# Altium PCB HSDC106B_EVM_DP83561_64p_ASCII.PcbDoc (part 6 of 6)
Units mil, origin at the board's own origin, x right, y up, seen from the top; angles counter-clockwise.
Board outline 8750.24 x 6394.7 mil, 6 copper layers (Top Layer, GND, SIG1, SIG2, GND1, Bottom Layer), stack 60.4 mil thick; 475 components, 330 nets, 1628 pads, 1086 vias.
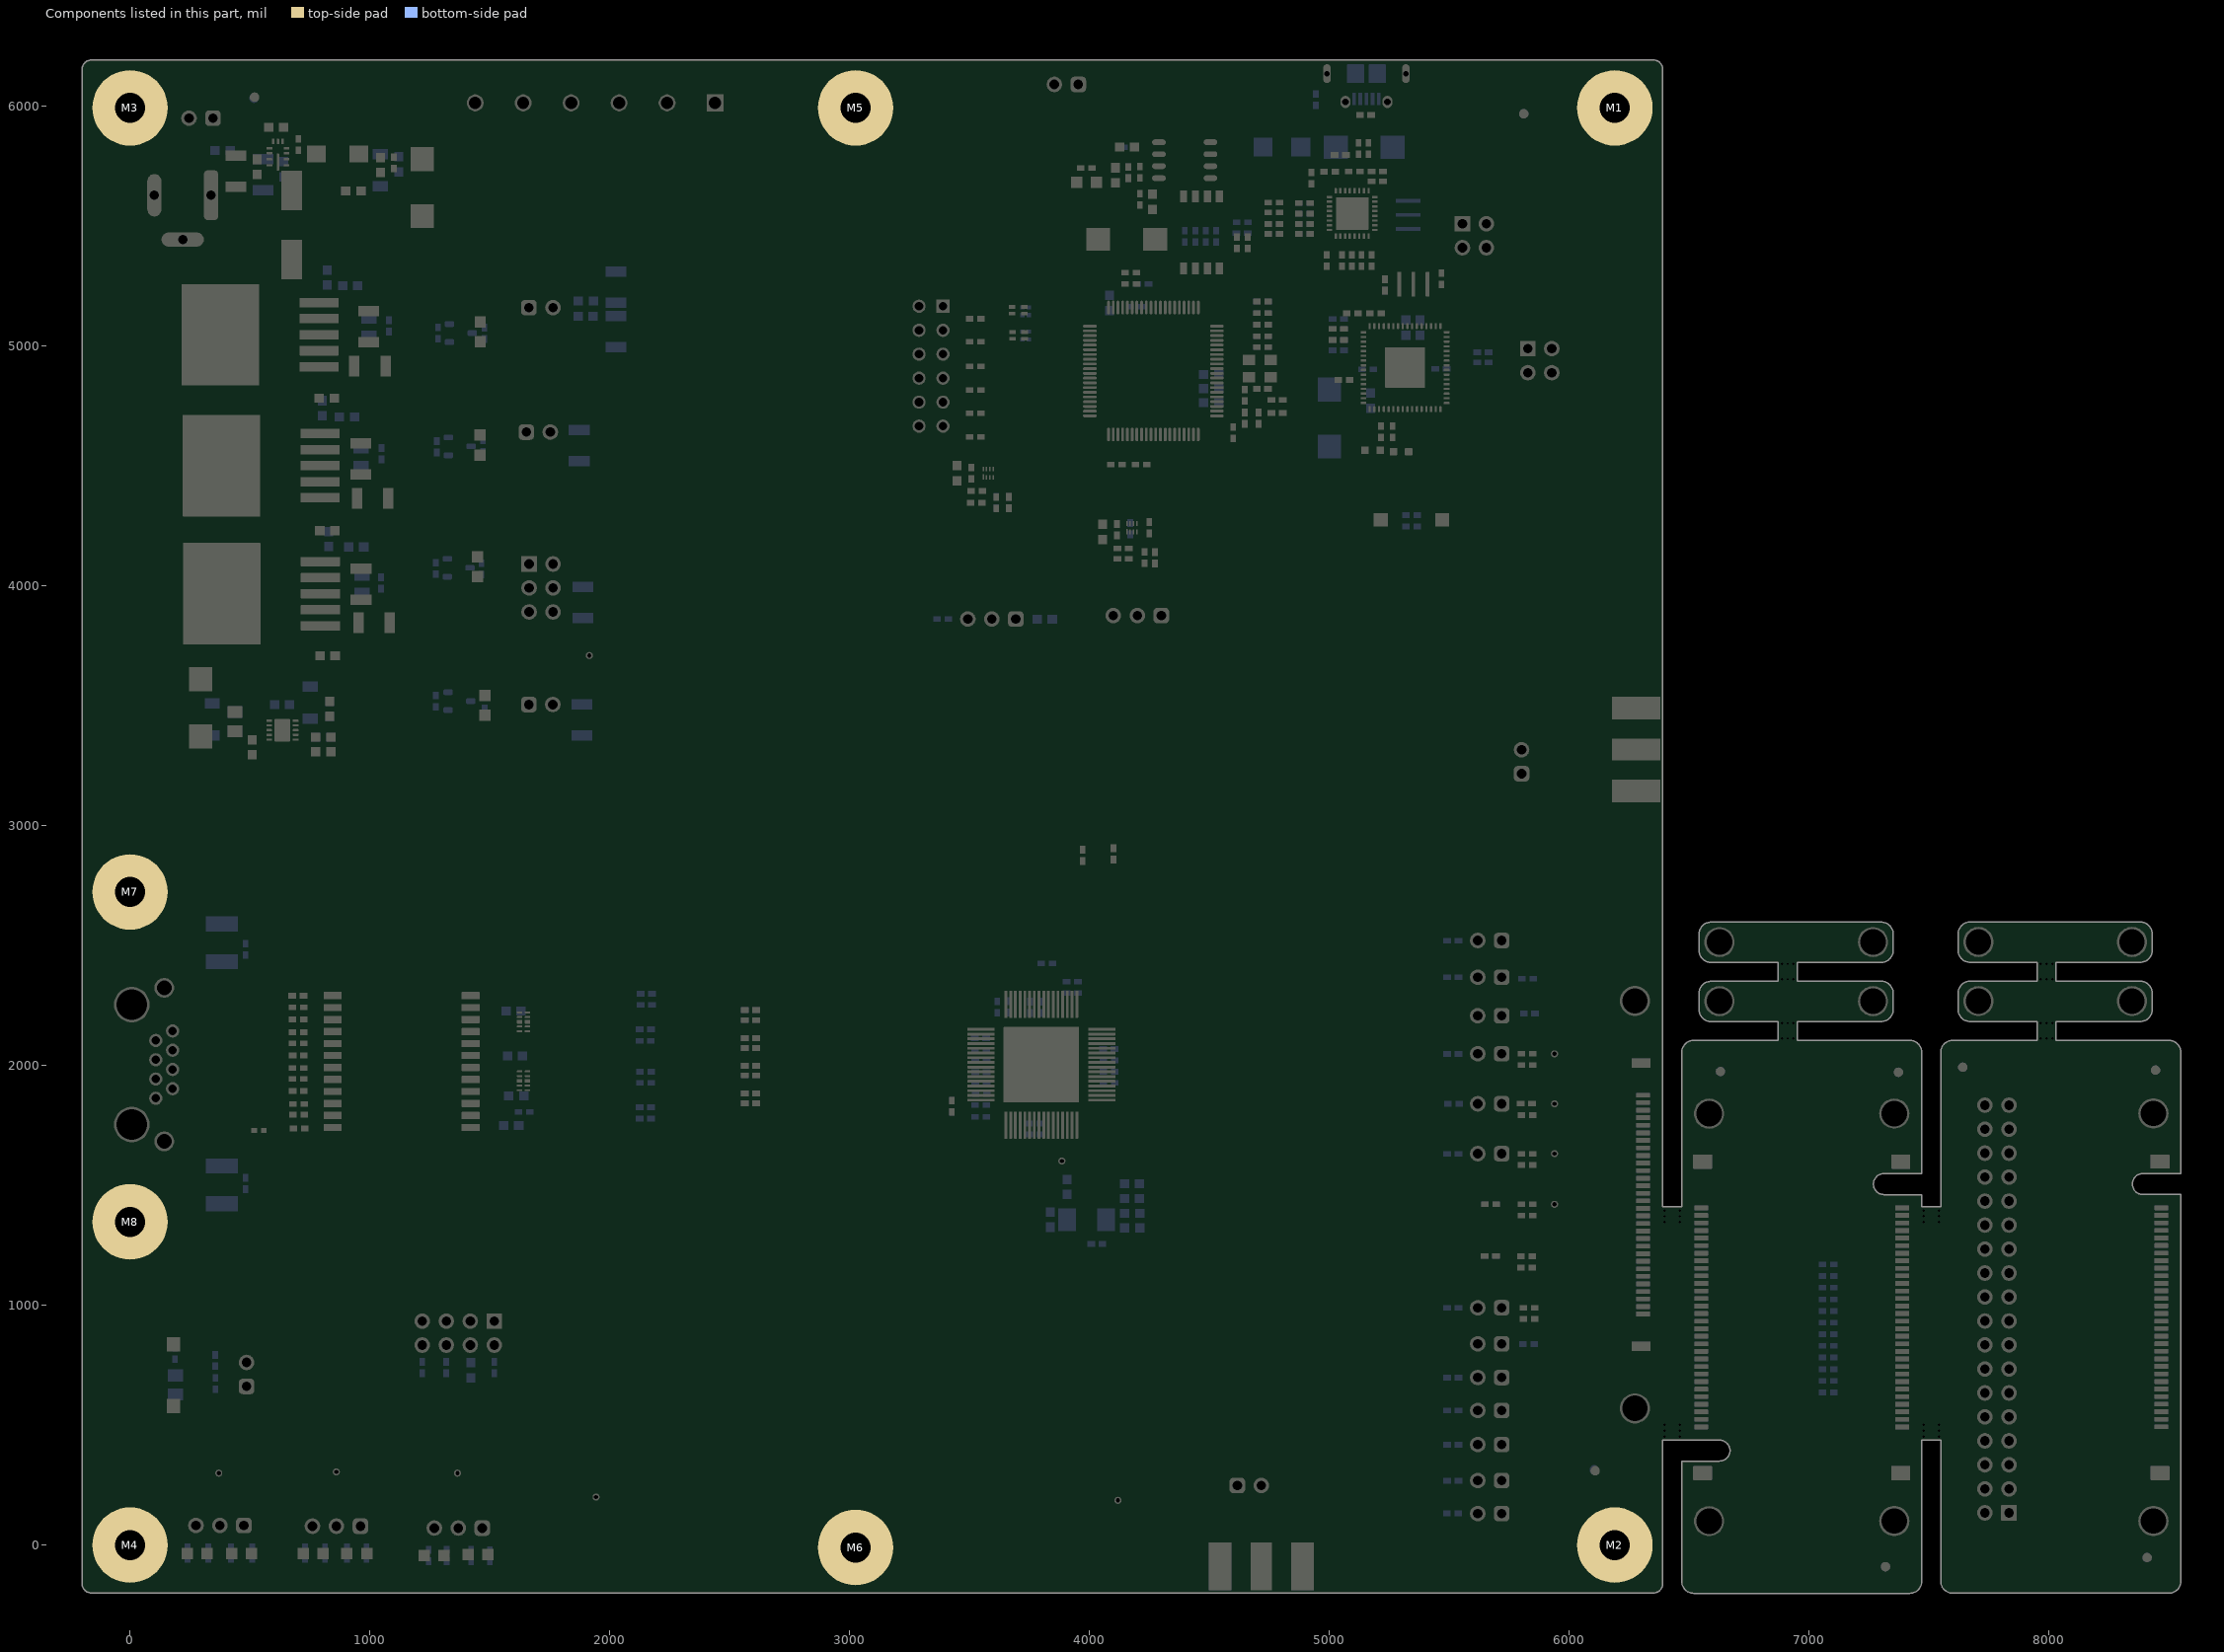
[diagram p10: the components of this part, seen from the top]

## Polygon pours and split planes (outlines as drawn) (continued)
5V-36V on Top Layer "5V-36V_L01_P641" (solid, remove dead copper, pour order 641): 405.6,5880.61 497.6,5880.61 564.6,5813.61 589.6,5813.61 592.6,5810.61 592.6,5776.61 590.6,5774.61 563.6,5774.61 534.6,5745.61 409.88,5745.61 396.6,5758.88 396.6,5871.61
5V-36V_jack on Top Layer "5V-36V_JACK_L01_P644" (solid, remove dead copper, pour order 644): 294.6,5968.61 294.6,5542.51 310.82,5526.29 363.62,5526.29 381.27,5543.94 381.27,5967.44 363.1,5985.61 311.6,5985.61
2V5 on Top Layer "Bottom Layer-No Net" (solid, pour order 661): 25 vertices, not listed, extent 707,4511.7 1703,4838.7
3V3 on Top Layer "Bottom Layer-No Net" (solid, pour order 671): 17 vertices, not listed, extent 708,3816.61 1713.83,4162.61
GND on Top Layer "Bottom Layer-No Net" (solid, pour order 677): 798,3634.7 788,3624.7 788,3498.7 793,3493.7 952,3493.7 956,3497.7 956,3624.7 946,3634.7
MCU_VCC on Top Layer "Bottom Layer-No Net" (solid, remove dead copper, pour order 676): 4091.6,5498.61 4091.6,5536.61 4074.6,5553.61 3941.6,5553.61 3906.6,5518.61 3906.6,5359.61 3913.6,5352.61 4089.15,5352.61 4091.6,5355.06 4091.6,5394.61
1V1 on Top Layer "Bottom Layer-No Net" (solid, pour order 672): 20 vertices, not listed, extent 676,3359.7 957,3477.7
GND on Top Layer "Bottom Layer-No Net" (solid, pour order 658): 1144,4973.7 1144,5065.7 1140,5069.7 961,5069.7 951,5059.7 951,4992.7 954,4989.7 1036,4989.7 1037,4988.7 1037,4849.7 1040,4846.7 1138,4846.7 1144,4852.7
5V on Top Layer "Bottom Layer-No Net" (solid, remove dead copper, pour order 680): 897.6,4947.3 897.6,4892.3 829.54,4824.24 829.54,4745.66 842.3,4732.9 978.2,4732.9 988,4742.7 988,4942.7 968,4962.7 913,4962.7
5V on Top Layer "Bottom Layer-No Net" (solid, remove dead copper, pour order 681): 971,3890.7 985,3876.7 985,3667.7 972,3654.7 848.5,3654.7 835.6,3667.61 835.6,3727.3 908,3799.7 908,3873.7 925,3890.7
5V on Top Layer "Bottom Layer-No Net" (solid, remove dead copper, pour order 679): 832.21,4208.7 829,4211.91 829,4266.7 902,4339.7 902,4399.7 912,4409.7 976,4409.7 979,4406.7 979,4221.7 966,4208.7
GND on Top Layer "Bottom Layer-No Net" (solid, pour order 674): 380.09,3448.61 357,3471.7 255,3471.7 236,3490.7 236,3660.7 240,3664.7 479,3664.7 491,3652.7 491,3472.66 466.95,3448.61
GND on Top Layer "Bottom Layer-No Net" (solid, pour order 665): 1048,4519.7 1056,4527.7 1158,4527.7 1165,4520.7 1165,4303.7 1159,4297.7 1149,4297.7 1051,4297.7 1048,4300.7
GND on Top Layer "Bottom Layer-No Net" (solid, pour order 668): 1059,3910.7 1154,3910.7 1159,3905.7 1159,3784.7 1153,3778.7 1055,3778.7 1052,3781.7 1052,3903.7
VDDA1P8_CD on Top Layer "VDDA1P8_CD_L01_P648" (solid, remove dead copper, pour order 648): 3569.04,2326.76 3569.04,2244.57 3615.74,2197.88 3647.98,2197.88 3657.59,2207.49 3657.59,2318.17 3640.85,2334.91 3575.83,2334.91
GND_1 on Bottom Layer "GND_2" (solid, remove dead copper, pour order 669): 17 vertices, not listed, extent 7582,-160 8512,2066
GND on Bottom Layer "GND_L06_P667" (solid, remove dead copper, pour order 667): 22 vertices, not listed, extent -160,-150.65 6359,6157.78
NetJ42_6 on Bottom Layer "Bottom Layer-No Net" (solid, remove dead copper, pour order 653): 20 vertices, not listed, extent 4921,5936.61 5356,6175.7
RJ45_ERTH on Bottom Layer "Bottom Layer-No Net" (solid, remove dead copper, pour order 657): -160,1186.2 -115.4,1141.61 111.6,1141.61 187.6,1217.61 187.6,1490.61 213.6,1517.35 480.62,1517.35 529,1565.73 529,1621.64 529,2418.64 485.36,2462.28 -110.72,2462.28 -160,2413
VDDIO on Bottom Layer "VDDIO_L06_P630" (solid, remove dead copper, pour order 630): 3749.44,2395.9 3804.55,2395.9 3815.75,2384.7 3815.75,2254.75 3811,2250 3743.39,2250 3740.79,2252.61 3740.79,2387.25
VDDA1P8_AB on Bottom Layer "VDDA1P8_AB_L06_P631" (solid, remove dead copper, pour order 631): 3473,1842.4 3473,1783.57 3482.28,1774.29 3538.9,1774.29 3538.9,1843.1 3532,1850 3480.6,1850
GND_2 on Bottom Layer "GND_2" (solid, remove dead copper, pour order 670): 27 vertices, not listed, extent 6502,-169 7453,2087
VDD1P0 on Bottom Layer "VDD1P0_L06_P636" (solid, remove dead copper, pour order 636): 26 vertices, not listed, extent 1722.67,1982.61 4305.94,3589.94
VDDIO on Bottom Layer "Bottom Layer-No Net" (solid, pour order 650): 27 vertices, not listed, extent 1720,3769.7 4305.6,4304.61
GND on Bottom Layer "GND_L06_P666" (solid, remove dead copper, pour order 666): 3710,1869 3789,1869 3794,1864 3794,1845 3765,1816 3765,1701 3761,1697 3722,1697 3717,1702 3717,1798 3702,1813 3702,1861
GND on Bottom Layer "GND_L06_P664" (solid, pour order 664): 512.07,1489 553,1448.07 553,1293 512,1252 316,1252 281,1287 281,1465 305,1489
5V-36V_jack on Bottom Layer "5V-36V_JACK_L06_P662" (solid, remove dead copper, pour order 662): 293.6,5985.61 293.6,5536.61 305.93,5524.27 369.96,5524.27 380.29,5534.61 380.29,5982.91 366.62,5996.59 304.58,5996.59
5V on Bottom Layer "Bottom Layer-No Net" (solid, remove dead copper, pour order 643): 309,3423.7 240,3423.7 223.6,3407.3 223.6,3292.1 252,3263.7 423.09,3263.7 476,3316.61 476,3418.7 471,3423.7 467,3423.7
MCU_VCC on Bottom Layer "MCU_VCC_L06_P663" (solid, remove dead copper, pour order 663): 4014.6,5804.61 4155,5804.61 4174.6,5785.01 4174.6,5728.8 4173.41,5727.61 4008.6,5727.61 4001.6,5734.61 4001.6,5791.61
1V8 on Bottom Layer "Bottom Layer-No Net" (solid, pour order 645): 19 vertices, not listed, extent 926,5059.7 1697,5279.7
3V3 on Bottom Layer "Bottom Layer-No Net" (solid, pour order 637): 29 vertices, not listed, extent 918,3703.7 1705,4266.7
5V on Bottom Layer "Bottom Layer-No Net" (solid, pour order 639): 17 vertices, not listed, extent 880.6,5655.61 1351.55,5878.61
5V-36V on Bottom Layer "5V-36V_L06_P632" (solid, remove dead copper, pour order 632): 714.23,5880.61 782.34,5812.5 782.34,5474.69 712.25,5404.61 605.6,5404.61 595.6,5414.61 595.6,5583.61 680.6,5668.61 680.6,5733.58 676.6,5737.58 417.9,5737.58 396.6,5758.88 396.6,5871.61 405.6,5880.61 506.1,5880.61
VDDA1P8 on Bottom Layer "Bottom Layer-No Net" (solid, pour order 647): 1717,5540.7 1942,5765.7 1941,5766.7 1941,6141.7 1951,6151.7 2113,6151.7 2125,6139.7 2125,5581.7 1890,5346.7 1890,5272.7 1891,5271.7 1891,5097.7 1886,5092.7 1727,5092.7 1717,5102.7
NetC116_1 on Bottom Layer "Bottom Layer-No Net" (solid, remove dead copper, pour order 654): 4965.1,5881.11 5023.6,5939.61 5070.15,5986.16 5104.19,5986.16 5114.54,5975.8 5114.54,5918.1 5086.7,5890.26 5086.7,5805.41 5061.4,5780.11 4996.94,5780.11 4916.03,5780.11 4837.03,5780.11 4831.03,5786.11 4831.03,5875.11 4837.03,5881.11
VDDA2P5 on Bottom Layer "Bottom Layer-No Net" (solid, pour order 649): 2594.68,4365.7 2610.5,4365.7 2636,4391.2 2636,4539.92 2600.96,4573.7 2265,4573.7 2130,4708.7 1931,4708.7 1928,4711.7 1728,4711.7 1725,4708.7 1725,4541.7 1735,4531.7 2032,4531.7 2198,4365.7
2V5 on Bottom Layer "Bottom Layer-No Net" (solid, pour order 646): 19 vertices, not listed, extent 912,4516.7 1702,4796.61
GND on Bottom Layer "Bottom Layer-No Net" (solid, pour order 642): 953,3492.7 957,3496.7 957,3623.7 947,3633.7 723,3633.7 713,3623.7 713,3503.7 724,3492.7
1V1 on Bottom Layer "Bottom Layer-No Net" (solid, pour order 640): 23 vertices, not listed, extent 641,3360.7 956,3536.7
VDDIO on Bottom Layer "VDDIO_L06_P633" (solid, remove dead copper, pour order 633): 3775.87,1573.61 3775.87,1769.88 3781.6,1775.61 3826.6,1775.61 3837.64,1764.56 3837.64,1575.39 3820.05,1557.8 3794.6,1557.8
VDDA1P8_AB on Bottom Layer "Top Layer-No Net 8" (solid, remove dead copper, pour order 660): 2781,4984.7 2872,4984.7 2875,4987.7 2875,5069.96 2868.26,5076.7 2178,5076.7 2173.92,5076.7 2100.13,5147.61 1912.6,5147.61 1910,5145.01 1910,5105.7 1914,5101.7 2053,5101.7 2170,4984.7
VDDA1P8_CD on Bottom Layer "Top Layer-No Net 8" (solid, remove dead copper, pour order 659): 18 vertices, not listed, extent 1911,5062.7 3109,5226.7
GND on Bottom Layer "Bottom Layer-No Net" (solid, remove dead copper, pour order 656): 5090,4645.7 5094,4641.7 5094,4480.7 5083,4469.7 4914,4469.7 4905,4478.7 4905,4640.7 4910,4645.7
USB_VBUS on Bottom Layer "Bottom Layer-No Net" (solid, pour order 652): 3932,5994.7 4030.02,5994.7 4167.6,5857.12 4167.6,5817.8 4213.29,5772.11 4771.1,5772.11 4791.6,5792.61 4791.6,5947.61 4764.6,5974.61 4287.6,5974.61 4188.5,6073.7 4109.51,6152.7 3924,6152.7 3915,6143.7 3915,6011.7
VDDIO on Bottom Layer "VDDIO_L06_P635" (solid, remove dead copper, pour order 635): 4339.6,1964.61 4400.6,2025.61 4446.6,2025.61 4451.6,2020.61 4451.6,1926.61 4432.6,1907.61 4101.74,1907.61 4088.6,1920.75 4088.6,1982.61 4094.95,1988.95 4221.25,1988.95 4245.6,1964.61
VDDA1P8_CD on Bottom Layer "VDDA1P8_CD_L06_P634" (solid, remove dead copper, pour order 634): 3569.44,2285.84 3602.68,2252.61 3677.6,2252.61 3677.6,2304.61 3646.62,2335.59 3596.76,2335.59 3569.44,2308.27
VDDIO on SIG2 "Bottom Layer-No Net" (solid, remove dead copper, pour order 694): 19 vertices, not listed, extent 161.88,-141.84 5964.85,4068
MCU_VCC on SIG2 "SIG2-MCU_VCC" (solid, remove dead copper, pour order 708): 35 vertices, not listed, extent 3353,4099 5551,5806.03
USB_VBUS on SIG2 "Bottom Layer-No Net" (solid, remove dead copper, pour order 693): 30 vertices, not listed, extent 3924,4404.7 6121.52,6171.7
GND_2 on SIG2 "GND_2" (solid, remove dead copper, pour order 717): 27 vertices, not listed, extent 6502,-169 7453,2087
RJ45_ERTH on SIG2 "Bottom Layer-No Net" (solid, remove dead copper, pour order 720): -160,1186.2 -115.4,1141.61 111.6,1141.61 187.6,1217.61 187.6,1490.61 213.6,1517.35 480.62,1517.35 529,1565.73 529,1621.64 529,2418.64 485.36,2462.28 -110.72,2462.28 -160,2413
GND_1 on SIG2 "GND_2" (solid, remove dead copper, pour order 713): 17 vertices, not listed, extent 7582,-160 8512,2066
VDDIO on SIG2 "Bottom Layer-No Net" (solid, pour order 684): 17 vertices, not listed, extent 982,3762.96 1823.64,6134.7
VDDA1P8_AB on SIG2 "Bottom Layer-No Net" (solid, remove dead copper, pour order 697): 17 vertices, not listed, extent 2678.8,1748.74 3639.99,5115.17
VDDA1P8_CD on SIG2 "Bottom Layer-No Net" (solid, remove dead copper, pour order 696): 3139.51,3267.14 3703.18,2703.47 3703.18,2328.31 3636.07,2261.2 3570.89,2261.2 3530.46,2301.63 3530.46,2588.77 2916.24,3196.17 2916.24,5152.59 2942.09,5178.45 3090.33,5178.45 3139.51,5129.27
VDD1P0 on SIG2 "Bottom Layer-No Net" (solid, remove dead copper, pour order 691): 20 vertices, not listed, extent 1726,3382.2 2337.17,6138.7
VDDA2P5 on SIG2 "Bottom Layer-No Net" (solid, remove dead copper, pour order 690): 1990,5696.7 1844,5550.7 1844,4378.7 1820,4353.7 1528,4353.7 1492,4389.7 1492,5682.7 1706,5896.7 1706,6118.7 1721,6133.7 1972,6133.7 1990,6115.7
VDDA2P5 on SIG2 "Bottom Layer-No Net" (solid, remove dead copper, pour order 695): 19 vertices, not listed, extent 2375.83,1889.05 3465.35,4561.03
OC_N on SIG1 "Bottom Layer-No Net" (solid, remove dead copper, pour order 692): 4908,5349.7 4908,5616.7 4919.5,5631.2 4932,5643.7 4992,5643.7 5016,5619.7 5016,5467.7 5036,5447.7 5131,5447.7 5144.81,5433.89 5144.81,5366.51 5099,5320.7 4937,5320.7
VDD1P0 on SIG1 "VDD1P0_L03_P698" (solid, remove dead copper, pour order 698): 22 vertices, not listed, extent 1728.77,1914.64 4279,3546.97
GND_2 on SIG1 "GND_2" (solid, remove dead copper, pour order 716): 27 vertices, not listed, extent 6502,-169 7453,2087
RJ45_ERTH on SIG1 "Bottom Layer-No Net" (solid, remove dead copper, pour order 721): -160,1186.2 -115.4,1141.61 111.6,1141.61 187.6,1217.61 187.6,1490.61 213.6,1517.35 480.62,1517.35 529,1565.73 529,1621.64 529,2418.64 485.36,2462.28 -110.72,2462.28 -160,2413
GND_1 on SIG1 "GND_2" (solid, remove dead copper, pour order 712): 17 vertices, not listed, extent 7582,-160 8512,2066
5V on SIG1 "Bottom Layer-No Net" (solid, pour order 688): 25 vertices, not listed, extent -169,3262.7 3895,6138.7
GND on SIG1 "Bottom Layer-No Net" (solid, remove dead copper, pour order 689): 5409,6174.7 5448,6135.7 5448,5757.7 5428,5737.7 4086,5737.7 4073,5750.7 4073,6168.7 4079,6174.7
1V8 on SIG1 "Bottom Layer-No Net" (solid, pour order 685): 19 vertices, not listed, extent 946.61,4043.7 1922,5306.7
1V1 on SIG1 "Bottom Layer-No Net" (solid, pour order 687): 852,3567.7 1361,3567.7 1394,3534.7 1693,3534.7 1701,3526.7 1701,3363.7 1689,3351.7 848,3351.7 839,3360.7 839,3554.7
3V3 on SIG1 "Bottom Layer-No Net" (solid, pour order 686): 17 vertices, not listed, extent 991,3592.7 1714,5110.7
GND on GND "GND_L02_P725" (solid, remove dead copper, pour order 725): 22 vertices, not listed, extent -160,-150.65 6359,6157.78
GND_2 on GND "GND_2" (solid, remove dead copper, pour order 715): 27 vertices, not listed, extent 6502,-169 7453,2087
RJ45_ERTH on GND "Bottom Layer-No Net" (solid, remove dead copper, pour order 722): -160,1186.2 -115.4,1141.61 111.6,1141.61 187.6,1217.61 187.6,1490.61 213.6,1517.35 480.62,1517.35 529,1565.73 529,1621.64 529,2418.64 485.36,2462.28 -110.72,2462.28 -160,2413
GND_1 on GND "GND_2" (solid, remove dead copper, pour order 711): 17 vertices, not listed, extent 7582,-160 8512,2066
GND on GND1 "GND_L05_P724" (solid, remove dead copper, pour order 724): 22 vertices, not listed, extent -160,-150.65 6359,6157.78
GND_2 on GND1 "GND_2" (solid, remove dead copper, pour order 718): 27 vertices, not listed, extent 6502,-169 7453,2087
RJ45_ERTH on GND1 "Bottom Layer-No Net" (solid, remove dead copper, pour order 719): -160,1186.2 -115.4,1141.61 111.6,1141.61 187.6,1217.61 187.6,1490.61 213.6,1517.35 480.62,1517.35 529,1565.73 529,1621.64 529,2418.64 485.36,2462.28 -110.72,2462.28 -160,2413
GND_1 on GND1 "GND_2" (solid, remove dead copper, pour order 714): 17 vertices, not listed, extent 7582,-160 8512,2066

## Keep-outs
Top Layer:
  circle w10: c5811,5969 r42.8
  circle w10: c6108.36,310.06 r42.8
  circle w10: c519,6038.7 r42.8
Keep-Out Layer:
  text ".Layer_Name" at 397,-2173.3 h60

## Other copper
Top Layer:
  text ".Layer_Name" at 480,-2173.79 h60
GND:
  text ".Layer_Name" at 480,-2173.79 h60
SIG1:
  text ".Layer_Name" at 480,-2173.79 h60
SIG2:
  text ".Layer_Name" at 480,-2173.79 h60
GND1:
  text ".Layer_Name" at 480,-2173.79 h60
Bottom Layer:
  text ".Layer_Name" at 558,-2173.79 h60

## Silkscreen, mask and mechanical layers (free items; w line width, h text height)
Top Overlay:
  drawing of 171 lines, arcs and shapes, not listed
  text "USB_VBUS" at 4020,6074 h60
  text "5V" at 3720,6070 h40
  text "GND" at 189.97,6022.65 h40
  text "5V" at 335.97,6016.65 h40
  text "5V" at 2471.6,5737.61 h40 r90
  text "GND" at 1465,5713 h40 r90
  text "VDD1P1" at 2240.6,5626.61 h40 r90
  text "VDDIO" at 1672.6,5622.61 h40 r90
  text "EZFET_RST" at 5493,5579 h30
  text "VDDA1P8" at 2035.6,5575.61 h40 r90
  text "VDDA2P5" at 1860.6,5550.7 h40 r90
  text "5V" at 408,5547 h40
  text "GND" at 5724.97,5487.96 h40
  text "GND" at 5722,5386 h40
  text "EZFET_TST" at 5505,5306.61 h30
  text "GND" at 3405,5288 h35
  text "RESETN" at 3044,5145 h30
  text "MSP_TST" at 5758,5063 h40
  text "INT_SUP_CUR_N" at 2842,5055 h30
  text "1V8" at 1574,5050 h40
  text "VDDA1P8" at 1719.6,5045.61 h40
  text "1V8" at 61,5034 h40
  text "GND" at 6003.78,4962.25 h40
  text "INT_ECC_N" at 2963,4951 h30
  text "GND" at 6009.78,4857.25 h40
  text "INT_STTMCHNE_N" at 2813,4855 h30
  text "MSP_RST" at 5770.78,4777.25 h40
  text "AUTO_RECOVER" at 2874,4755 h30
  text "INT_PWDN" at 2996,4652 h30
  text "2V5" at 58.95,4539.7 h40
  text "2V5" at 1582,4519 h40
  text "VDDA2P5" at 1750,4518 h40
  text "MSP Reset" at 5202,4385 h40
  text "1V8" at 1495,4069.7 h40
  text "2V5" at 1496,3976.7 h40
  text "3V3" at 56,3969 h40
  text "INT_PWDN" at 3467,3941 h30
  text "VDDIO" at 1884,3898 h40 r90
  text "3V3" at 1497,3882.7 h40
  text "MDC" at 4030,3783 h30
  text "GND" at 4301,3783 h30
  text "MDIO" at 4152,3779 h30
  text "1V1" at 61,3496 h40
  text "1V1" at 1604,3410 h30
  text "VDD1P1" at 1716,3401 h40
  text "CLKOUT" at 5887,3305 h35
  text "GND" at 5883,3186 h40
  text "PU" at 5572,2590 h25
  text "SMI_DISABLE" at 5787,2505 h35
  text "PU" at 5569,2431 h25
  text "CRS (MII/RGMII)" at 5785,2364 h35
  text "GND" at 5466,2195 h25
  text "COL" at 5815,2190 h35
  text "PU" at 5571,2114 h25
  text "GND" at 5977,2029 h40
  text "RX_CTRL (MIRROR_EN)" at 4901,2012 h35
  text "MAC interface breakout" at 7774,1983 h60
  text "PU" at 5567.6,1904.01 h25
  text "RX_D3 (OPMODE_1)" at 5003,1828 h35
  text "RX_ER_1" at 7906,1824 h30
  text "GND" at 5977,1823 h40
  text "MDIO_1" at 7904,1719 h30
  text "PU" at 5565.6,1699.61 h25
  text "MDC_1" at 7909,1624 h30
  text "RX_D2 (OPMODE_2)" at 4992,1616 h35
  text "GND" at 5978,1612 h40
  text "GTX_CLK_1" at 7909,1525 h30
  text "DP83561EVM" at 799,1444 h100
  text "RX_CLK_1" at 7908,1424 h30
  text "GND" at 5974,1402 h40
  text "RX_D1 (PHY_ADD[3:2])" at 4869,1385 h35
  text "TX_D0_1" at 7909,1322 h30
  text "HSDC106E1" at 869,1220 h100
  text "RX_D0_1" at 7909,1218 h30
  text "RX_D0 (PHY_ADD[1:0])" at 4859,1168 h35
  text "TX_D1_1" at 7907,1115 h30
  text "PU" at 5579,1060 h25
  text "RX_D1_1" at 7912.47,1025.08 h30
  text "GND" at 1311.77,1000.41 h35
  text "GND_1" at 7653,1001 h40 r90
  text "RX_CLK" at 5334,981 h35
  text "TX_D2_1" at 7904.47,920.08 h30
  text "RESET_N" at 140,917 h35
  text "RX_D2_1" at 7908.47,823.08 h30
  text "GND" at 5465,809 h25
  text "RX_ER" at 5814,804 h35
  text "RESET_N" at 561,743 h30
  text "TX_D3_1" at 7911.47,718.08 h30
  text "AUTO_RECOVER" at 5120,685 h35
  text "GND" at 555,633 h30
  text "RX_D3_1" at 7912.47,618.08 h30
  text "JTAG_TDO (OPMODE_0)" at 4893,543 h35
  text "JTAG_TDI" at 1225.6,516.61 h35 r90
  text "TX_CTRL_1" at 7915.47,517.08 h30
  text "JTAG_CLK" at 1432.56,499.61 h35 r90
  text "JTAG_TMS" at 1529.25,493.41 h35 r90
  text "JTAG_TDO" at 1325.88,493.05 h35 r90
  text "RX_CTRL_1" at 7931.47,417.08 h30
  text "SUPPLY MODE (TRIPLE/DUAL)" at 4685,403 h35
  text "ANEGSEL_1" at 223,401 h35
  text "ANEGSEL_0" at 728,401 h35
  text "ANEG_DIS" at 1223.6,391.61 h35
  text "RESETN_1" at 7916.47,321.08 h30
  text "GND" at 898,289 h40
  text "GND" at 1416,284 h40
  text "GND" at 405,282 h40
  text "GND" at 1886,244 h40
  text "CRS_1" at 7922.47,226.08 h30
  text "VDDIOSEL_0" at 5790,193 h35
  text "GND" at 4417,178 h40
  text "PU LED0 PD" at 1215,149 h35
  text "PU LED2 PD" at 204,146 h35
  text "PU LED1 PD" at 705,146 h35
  text "EXT_REF_CLK" at 4603,124 h35
  text "COL_1" at 7913.47,119.08 h30
  text "VDDIOSEL_1" at 5644,20 h35
  text "RGMII back-to-back connector" at 6488,-116 h60
  text ".Layer_Name" at 464,-2173.79 h60
Bottom Overlay:
  circle w10: c4100.65,1273.65 r2
  circle w10: c705,3446.77 r2
  circle w10: c1317,3451 r2
  circle w10: c1319,4003 r2
  circle w10: c1320,4508 r2
  circle w10: c1319,4975 r2
  circle w10: c485,5777 r2
  circle w10: c978,5806 r2
  circle w6: c5419,5610 r10.48
  circle w7: c5104.6,5984.61 r7.69
  lines w6: 3473,2127 3473,1364 3481,1356 3592,1356 3603,1367 3603,1438
  text ".Layer_Name" at 480,-2173.79 h60
Top Paste:
  text ".Layer_Name" at 377,-2173.79 h60
Bottom Paste:
  text ".Layer_Name" at 377,-2193.79 h60
Top Solder:
  text ".Layer_Name" at 377,-2173.79 h60
  text ".Layer_Name" at 377,-2173.79 h60
Bottom Solder:
  text ".Layer_Name" at 377,-2193.79 h60
Drill Guide:
  text ".Layer_Name" at 395,-2170.3 h60
M1 Board Outline:
  lines w10: 6390.55,437.61 6390.55,-160 cw(c6350.55,-160) 6350.55,-200 -160,-200 cw(c-160,-160) -200,-160 -200,6153.7 cw(c-160,6153.7) -160,6193.7 6350.55,6193.7 cw(c6350.55,6153.7) 6390.55,6153.7 6390.55,1410.43 ; 6390.55,516.54 6390.55,860.94 6236.02,860.94 cw(c6235.46,893.9) 6202.5,893.34 cw(c6236.53,893.85) 6236.02,927.87 6390.55,927.87 6390.55,1331.61 ; 6390.84,516.54 6468.58,516.54 6469.29,1173.2 6469.29,1318.87 6469.29,1331.69 ; 6390.84,1331.69 6468.29,1331.69 ; 6390.84,1410.43 6468.29,1410.43 ; 6391.84,437.8 6469.58,437.8 6627.15,437.8 cw(c6627.15,394.35) 6670.6,394.35 6670.6,393.93 cw(c6627.06,393.93) 6627.06,350.39 6469.58,350.39 6469.29,297.49 ; 6469.29,296.2 6469.29,-151 ccw(c6519.29,-151) 6519.29,-201 7420.39,-201 ccw(c7420.39,-151) 7470.39,-151 7470.39,200.76 7470.39,346.43 7470.39,438.1 ; 6469.29,1410.43 6469.29,2054.61 cw(c6519.29,2054.61) 6519.29,2104.61 6871.81,2104.61 6871.81,2183.35 6591.84,2183.35 cw(c6591.84,2233.35) 6541.84,2233.35 6541.84,2301.35 cw(c6591.84,2301.35) 6591.84,2351.35 6871.81,2351.35 6871.81,2430.09 6591.84,2430.09 cw(c6591.84,2480.09) 6541.84,2480.09 6541.84,2548.09 cw(c6591.84,2548.09) 6591.84,2598.09 7301,2598.09 ; 7301,2351.35 6950.55,2351.35 6950.55,2430.09 7301.13,2430.09 ; 7301.13,2183.35 6950.55,2183.35 6950.55,2104.61 7420.39,2104.61 cw(c7420.39,2054.61) 7470.39,2054.61 7470.39,1549.13 ; 7301.13,2183.47 ccw(c7301.13,2233.47) 7351.13,2233.47 7351.13,2301.47 ccw(c7301.13,2301.47) 7301.13,2351.47 ; 7301.13,2430.21 ccw(c7301.13,2480.21) 7351.13,2480.21 7351.13,2548.21 ccw(c7301.13,2548.21) 7301.13,2598.21 ; 7469.7,1461.72 7312.13,1461.72 cw(c7312.13,1505.17) 7268.68,1505.17 7268.68,1505.59 cw(c7312.22,1505.59) 7312.22,1549.13 7469.7,1549.13 ; 7470.39,516.84 7470.39,1144.69 7470.39,1223.43 7470.39,1327.61 ; 7470.39,1410.74 7470.39,1461.72 ; 7470.68,516.84 7548.42,516.84 7549.13,1173.5 7549.13,1319.17 7549.13,1332 ; 7470.68,1332 7548.13,1332 ; 7470.68,1410.74 7548.13,1410.74 ; 7471.68,438.1 7549.42,438.1 7549.42,350.7 7549.13,297.8 ; 7549.13,296.5 7549.13,-150.69 ccw(c7599.13,-150.69) 7599.13,-200.69 8500.24,-200.69 ccw(c8500.24,-150.69) 8550.24,-150.69 8550.24,201.06 8550.24,346.73 8550.24,1144.99 8550.24,1223.73 8550.24,1462.03 ; 7549.13,1410.74 7549.13,2054.91 cw(c7599.13,2054.91) 7599.13,2104.91 7951.65,2104.91 7951.65,2183.65 7671.68,2183.65 cw(c7671.68,2233.65) 7621.68,2233.65 7621.68,2301.65 cw(c7671.68,2301.65) 7671.68,2351.65 7951.65,2351.65 7951.65,2430.39 7671.68,2430.39 cw(c7671.68,2480.39) 7621.68,2480.39 7621.68,2548.39 cw(c7671.68,2548.39) 7671.68,2598.39 7951.65,2598.39 8030.39,2598.39 8380.84,2598.39 ; 8380.84,2351.65 8030.39,2351.65 8030.39,2430.39 8380.97,2430.39 ; 8380.97,2183.65 8030.39,2183.65 8030.39,2104.91 8500.24,2104.91 cw(c8500.24,2054.91) 8550.24,2054.91 8550.24,1549.43 ; 8380.97,2183.78 ccw(c8380.97,2233.78) 8430.97,2233.78 8430.97,2301.78 ccw(c8380.97,2301.78) 8380.97,2351.78 ; 8380.97,2430.52 ccw(c8380.97,2480.52) 8430.97,2480.52 8430.97,2548.52 ccw(c8380.97,2548.52) 8380.97,2598.52 ; 8549.54,1462.03 8391.97,1462.03 cw(c8391.97,1505.48) 8348.52,1505.48 ; 8549.54,1549.43 8392.06,1549.43 ccw(c8392.06,1505.89) 8348.52,1505.89 ; 8348.52,1505.48 8348.52,1505.89 ; 8348.52,1505.48 8348.52,1505.89
  text ".layer_name" at 405,-2183.79 h60
M2 Board Dimensions:
  rectangle: -75,-1715.3 300,-1590.3
  rectangle: -200,-1590.3 -75,-1465.3
  lines w7: -200,-1590.3 800,-1590.3 ; -75,-1715.3 -75,-1465.3 ; 50,-1715.3 50,-1465.3 ; 300,-1715.3 300,-1465.3 ; 550,-1715.3 550,-1465.3 ; -200,-1715.3 -200,-1465.3 800,-1465.3 800,-1715.3 -200,-1715.3
M3 3D STEP Top:
  text ".Layer_Name" at 377,-2173.79 h60
M4 3D STEP Bottom:
  text ".Layer_Name" at 377,-2193.79 h60
M5 Assembly Top:
  circle w10: c8434,1442 r5.39
  circle w10: c7842,40 r5.39
  circle w10: c7363,1441 r5.39
  circle w10: c6260,945 r5.39
  circle w10: c6625,491 r5.39
  circle w10: c5795,140 r5.39
  circle w10: c5792,276 r5.39
  circle w10: c5795,434 r5.39
  circle w10: c5790,564 r5.39
  circle w10: c5791,698 r5.39
  circle w10: c5792,839 r5.39
  circle w10: c5795,1029 r5.39
  circle w10: c5791,1676 r5.39
  circle w10: c5797.98,1890.58 r5.39
  circle w10: c5801.34,2098.82 r5.39
  circle w10: c5791,2210 r5.39
  circle w10: c5795,2361 r5.39
  circle w10: c5801.83,2525.66 r5.39
  circle w10: c6122,3335 r5.39
  circle w10: c3460,2158 r5.39
  circle w10: c4599,323 r5.39
  circle w10: c4748.47,62.6 r5.39
  circle w10: c1557,67 r5.39
  circle w10: c1042,74 r5.39
  circle w10: c554.69,83.25 r5.39
  circle w10: c115,534 r5.39
  circle w10: c557,647 r5.39
  circle w10: c1618,937 r5.39
  circle w10: c1420,1694 r5.39
  circle w10: c99,1605 r5.39
  circle w10: c747.71,3771.14 r5.39
  circle w10: c731,4863 r5.39
  circle w10: c737,4304 r5.39
  circle w10: c5879,3193 r5.39
  circle w10: c1634,3596 r5.39
  circle w10: c1654,4182 r5.39
  circle w10: c1644,4721 r5.39
  circle w10: c1631,5243 r5.39
  circle w10: c3753,5021 r5.39
  circle w10: c3753,5128 r5.39
  circle w10: c3465,5176 r5.39
  circle w10: c3760.51,3852.97 r5.39
  circle w10: c4384,3867 r5.39
  circle w10: c5507,4336 r5.39
  circle w10: c5289,5196 r5.39
  circle w10: c4035,6085 r5.39
  circle w10: c766,5927 r5.39
  circle w10: c393,5587 r5.39
  circle w10: c416,5963 r5.39
  lines w6: 444,811.76 435.95,811.76 ; 679,5709 714,5709 ; 695,5693 695,5728 ; 435.95,811.76 435.95,611.76 535.95,611.76 535.95,811.76 435.95,811.76 ; 195.6,5900.61 195.6,6000.61 395.6,6000.61 395.6,5900.61 195.6,5900.61 ; 1602,4591.61 1602,4691.61 1802,4691.61 1802,4591.61 1602,4591.61 ; 4566.6,198.61 4566.6,298.61 4766.6,298.61 4766.6,198.61 4566.6,198.61 ; 5568.6,2257.61 5570.2,2256.01 5570.2,2159.2 5767,2159.2 5768.6,2157.61 5768.6,2257.61 5568.6,2257.61 ; 5568.99,789.65 5568.99,889.65 5768.99,889.65 5768.99,789.65 5568.99,789.65 ; 5751.67,3166.74 5751.67,3366.74 5851.67,3366.74 5851.67,3166.74 5751.67,3166.74
  lines w10: -492,-2245.47 6108,-2245.47 ; -492,-2042.13 6110,-2042.13 ; -492,-1838.8 -492,-2448.8 3513,-2448.8 6110,-2448.8 6110,-1838.8 -491.5,-1838.8 -491.5,-2448.8 1084,-2448.8 ; 1973,-2448.8 1973,-1838.8 ; 3240,-2042.13 3240,-1838.8 ; 4080,-2042.13 4080,-1838.8 ; 4702,-2455.3 4702,-2252.47 ; 6919,2755 6799,2635 6797,2635 ; 6797,2635 6831,2643 6797,2663 6797,2635
  text "4) SMALL STIRIPS AND MOUNTING HOLES ADDED IN DESIGN" at 6710.78,2931 h50
  text "THOSE ARE DESIGN REQUIREMENT. WHILE SHIPPING BOARDS, PLEASE HAND OVER TO CUSTOMER" at 6856.78,2843 h50
  text "STRIPS DESIGN REQUIREMENT" at 6931,2741 h50
  text "COMPONENTS MARKED 'DNP' SHOULD NOT BE POPULATED." at 2913.5,-1569.8 h60
  text "ASSEMBLY VARIANT:" at 2913,-1685.3 h60
  text ".VariantName" at 3949,-1685.3 h60
  text "PCB VIEWED FROM TOP SIDE" at -428.5,-1970.97 h60
  text "BOARD #:" at 2048,-1970.97 h60
  text "REV:" at 3438,-1970.97 h60
  text ".PCB_rev" at 3729.5,-1970.97 h60
  text "SVN REV:" at 4276,-1970.97 h60
  text ".VersionControl_RevNumber" at 4782,-1970.97 h60
  text ".PRJ_Number" at 2532,-1979.3 h50
  text "Layer Name:" at -393,-2158.01 h60
  text ".Layer_Name" at 480,-2173.79 h60
  text "NA" at 2466,-2173 h60
  text "TID #:" at 2048,-2174.3 h60
  text "PLOT NAME =" at -473,-2379 h50
  text ".plot_File_Name" at 81,-2379 h50
  text "GENERATED    :" at 2050,-2379.64 h60
  text ".Print_Date" at 2919.5,-2379.64 h60
  text ".Print_Time" at 3648.5,-2379.64 h60
  text "TEXAS INSTRUMENTS" at 4913,-2379.64 h60
M6 Assembly Bottom:
  circle w10: c4108,1271 r2.01
  circle w10: c1320,3446 r2.01
  circle w10: c1319,3995 r2.01
  circle w10: c1317.85,4498.13 r2.01
  circle w10: c1321,4967 r2.01
  circle w10: c5109.36,5980.98 r2.01
  lines w6: 1312,4644.7 1318,4644.7 1413,4644.7 1413,4606.7 ; 1315,5115.7 1331,5115.7 ; 1317,4520.7 1412,4520.7 1412,4557.7 ; 1361,4125.7 1412,4125.7 1412,4104.7 ; 1363,3566.7 1414,3566.7 1414,3545.7 ; 1368,4027.7 1411,4027.7 1411,4052.7 ; 1370,3468.7 1413,3468.7 1413,3493.7 ; 1417,5028.7 1417,4991.7 1322,4991.7 1315,4991.7 1315,4993.7 1315,5113.7 1317,5115.7 1323,5115.7 1418,5115.7 1418,5077.7
  lines w10: -492.5,-2042.63 6109.5,-2042.63 ; -490.5,-2245.97 6109.5,-2245.97 ; 915.5,-2455.8 915.5,-2252.97 ; 1537.5,-2042.63 1537.5,-1839.3 ; 2377.5,-2042.63 2377.5,-1839.3 ; 3644.5,-2449.3 3644.5,-1839.3 ; 4533.5,-2449.3 6109,-2449.3 6109,-1839.3 -492.5,-1839.3 -492.5,-2449.3 2104.5,-2449.3 6109.5,-2449.3 6109.5,-1839.3
  text "COMPONENTS MARKED 'DNP' SHOULD NOT BE POPULATED." at 5902,-1633.3 h60
  text ".VariantName" at 4858,-1749.3 h60
  text "ASSEMBLY VARIANT:" at 5897,-1749.3 h60
  text ".PRJ_Number" at 3061,-1967.47 h50
  text ".VersionControl_RevNumber" at 835.5,-1971.47 h60
  text "SVN REV:" at 1341.5,-1971.47 h60
  text ".PCB_rev" at 1888,-1971.47 h60
  text "REV:" at 2179.5,-1971.47 h60
  text "BOARD #:" at 3569.5,-1971.47 h60
  text "PCB VIEWED FROM BOTTOM SIDE" at 6046,-1971.47 h60
  text "Layer Name:" at 6022,-2165.01 h60
  text ".Layer_Name" at 5285,-2167 h60
  text "NA" at 3024,-2174.8 h60
  text "TID #:" at 3569.5,-2174.8 h60
  text "PLOT NAME =" at 6099,-2375 h50
  text ".plot_File_Name" at 5539,-2378 h50
  text "TEXAS INSTRUMENTS" at 704.5,-2380.14 h60
  text ".Print_Time" at 1969,-2380.14 h60
  text ".Print_Date" at 2698,-2380.14 h60
  text "GENERATED    :" at 3567.5,-2380.14 h60
M7 LPKF Text Top:
  text ".Layer_Name" at 480,-2173.79 h60
M8 LPKF Text Bottom:
  text ".Layer_Name" at 480,-2173.79 h60
M9 Title Sheet:
  lines w10: -691.5,-273.8 -491.5,-273.8 ; -691.5,2101.2 -491.5,2101.2 ; -691.5,4476.2 -491.5,4476.2 ; 1808.5,-2648.8 1808.5,-2448.8 ; 1808.5,6651.2 1808.5,6851.2 ; 4308.5,-2648.8 4308.5,-2448.8 ; 4308.5,6651.2 4308.5,6851.2 ; 6121,-2448.8 6121,-1838.8 11103.5,-1838.8 ; 6808.5,-2648.8 6808.5,-2448.8 ; 9308.5,-2648.8 9308.5,-2448.8 ; 9308.5,6651.2 9308.5,6851.2 ; 11103.5,-2448.8 11103.5,-1838.8 ; 11103.5,-2138.8 14103.5,-2138.8 ; 11103.5,-1538.8 14103.5,-1538.8 ; 11104.5,-944.8 14104.5,-944.8 ; 11808.5,-2648.8 11808.5,-2448.8 ; 11808.5,6651.2 11808.5,6851.2 ; 12608.5,-2438.8 12608.5,-1838.8 ; 14103.5,-1838.8 11103.5,-1838.8 ; 14103.5,-1238.8 11103.5,-1238.8 ; 14108.5,-1248.8 14108.5,-2448.8 ; 14108.5,-444.3 11104.5,-444.3 11103.5,-444.3 11103.5,-944.8 11103.5,-1238.8 ; 14108.5,-273.8 14308.5,-273.8 ; 14108.5,2101.2 14308.5,2101.2 ; 14108.5,4476.2 14308.5,4476.2 ; 11103.5,-1838.8 11103.5,-1238.8 ; 14108.5,-2448.8 -491.5,-2448.8 -491.5,6651.2 14108.5,6651.2 14108.5,-2448.8 ; -691.5,-2648.8 14308.5,-2648.8 14308.5,6851.2 -691.5,6851.2 -691.5,-2648.8
  text "1" at 539.84,6721.2 h70
  text "2" at 3035.5,6721.2 h70
  text "3" at 5524.84,6721.2 h70
  text "5" at 10530.5,6721.2 h70
  text "6" at 13035.5,6721.2 h70
  text "A" at -616.5,5578.2 h70
  text "A" at 14183.5,5578.2 h70
  text "B" at -616.5,3198.2 h70
  text "B" at 14183.5,3198.2 h70
  text "C" at -616.5,823.2 h70
  text "C" at 14183.5,823.2 h70
  text "PROJECT TITLE:" at 11143.5,-1037.8 h45
  text ".prj_title" at 11193.5,-1171.13 h70
  text "DESIGNED FOR:" at 11143.5,-1338.8 h45
  text "TI" at 11193.5,-1478.8 h70
  text "D" at -616.5,-1546.8 h70
  text "D" at 14183.5,-1546.8 h70
  text "FILE NAME:" at 11143.5,-1638.8 h45
  text ".PCB_File_Name_No_Path" at 11193.5,-1758.8 h70
  text "Texas Instruments (TI) and/or its licensors do not warrant the accuracy or completeness of this specification" at 6174,-1920.64 h45
  text "ENGINEER:" at 11143.5,-1928.8 h45
  text "LAYOUT BY:" at 12648.5,-1928.8 h45
  text "or any information contained therein. TI and/or its licensors do not warrant that this design will meet" at 6129.01,-2033.3 h45
  text "Justin" at 11193.5,-2083.79 h70
  text "Tessolve" at 12699,-2083.79 h70
  text "the specifications, will be suitable for your application or fit for any particular purpose, or will operate in" at 6129.01,-2145.97 h45
  text "ALTIUM DESIGNER VERSION:" at 12648.5,-2238.8 h45
  text "an implementation. TI and/or its licensors do not warrant that the design is production worthy. You should" at 6129.01,-2258.63 h45
  text "completely validate and test your design implementation to confirm the system functionality for your application." at 6174,-2371.3 h45
  text ".print_Scale" at 11193.5,-2372.13 h70
  text ".Application_BuildNumber" at 12699,-2372.13 h70
  text "1" at 539.84,-2578.8 h70
  text "2" at 3035.5,-2578.8 h70
  text "3" at 5524.84,-2578.8 h70
  text "4" at 8031.51,-2578.8 h70
  text "5" at 10530.5,-2578.8 h70
  text "6" at 13035.5,-2578.8 h70
M10 Fab Notes:
  drawing of 193 lines, arcs and shapes, not listed
  text "DESIGN INFORMATION" at 12181.02,4594.7 h60
  text "MIN. TRACK WIDTH:" at 11536.46,4414.7 h60
  text "6" at 12632.7,4414.7 h60
  text "MIL" at 12787.46,4414.7 h60
  text "MIN. CLEARANCE:" at 11536.46,4282.7 h60
  text "MIL" at 12787.46,4282.7 h60
  text "4.6" at 12568,4281 h60
  text "18" at 12600.6,4151.61 h60
  text "MIN. VIA PAD SIZE:" at 11536.46,4150.7 h60
  text "MIL" at 12787.46,4150.7 h60
  text "FAB NOTES:" at 6557.6,4030.61 h50
  text "0.127mm (5MIL)" at 12231.46,4008.99 h60
  text "MINIMUM ANNULAR RING" at 11207.23,4004.7 h60
  text "EXTERNAL" at 12939.46,4004.7 h60
  text "1)ALL VIAS ARE TENTED OTHER THAN THERMAL VIAS.." at 6762.38,3901.77 h50
  text "PER" at 11407.23,3886.7 h60
  text "IPC-D-275 CLASS 2 LEVEL C" at 11627.23,3886.7 h60
  text "2)IF NEED COPPER THIEVING CAN BE ADDED BASED ON COPPER BALANCING CALCULATION" at 6762.38,3792.36 h50
  text "MIL, HOLES" at 13115.46,3774.41 h60
  text "+/-" at 12723,3773.7 h60
  text "+/-" at 13577,3773.7 h60
  text "REGISTRATION TOLERANCES:" at 11207.23,3768.7 h60
  text "METAL" at 12407,3768.7 h60
  text "5" at 12983.2,3768.7 h60
  text "3" at 13816.2,3768.7 h60
  text "MIL" at 13932.46,3768.7 h60
  text "AND MAINTAIN 100MIL SPACING FROM ANY FUNCTIONAL CONDUCTOR." at 6850.38,3676.77 h50
  text "3)VENDOR MAY ADJUST SOLDERMASK WHEREVER SOLDERMASK PADS ARE SAME SIZE(1:1)" at 6762.38,3570.77 h50
  text "MATERIAL:" at 11132.46,3559.24 h60
  text "AS PER MANUFACTURING CAPABILITIES AND ALL OTHER SOLDERMASK PADS SHALL NOT BE MODIFIED" at 6850.38,3457.77 h50
  text "FR-4 High Tg" at 12118.9,3418.91 h60
  text "FR-408" at 11553.46,3410.34 h60
  text "X" at 11965.46,3410.34 h60
  text "OTHER" at 13041.46,3410.34 h60
  text "PROVIDED NO ADJACENT COPPER IS EXPOSED AND NO CONFLICT PRODUCED WITH ANY STATED" at 6850.38,3356.77 h50
  text "\"VIA TENTING/COVERING\" REQUIREMENTS." at 6850.38,3263.77 h50
  text "62 MIL (1.6mm) +/-10%" at 11873.56,3247.62 h60
  text "THICKNESS:" at 11207.23,3243.34 h60
  text "X" at 11745.4,3243.34 h60
  text "OTHER" at 13158.46,3243.34 h60
  text "4) SMALL STIRIPS AND MOUNTING HOLES ADDED IN DESIGN" at 6762.78,3091 h50
  text "TOLERANCE:" at 11207.23,3085.34 h60
  text "X" at 12046.53,3085.34 h60
  text "ANSI IPC-6012 TYPE 3 CLASS 2" at 12233.48,3085.34 h60
  text "THOSE ARE DESIGN REQUIREMENT. WHILE SHIPPING BOARDS, PLEASE HAND OVER TO CUSTOMER" at 6908.78,3003 h50
  text "OTHER +/-" at 12233.46,2929.34 h60
  text "BOW & TWIST:" at 11207.23,2772.34 h60
  text "X" at 12046.53,2772.34 h60
  text "ANSI IPC-6012 TYPE 3 CLASS 2" at 12233.48,2772.34 h60
  text "STRIPS DESIGN REQUIREMENT" at 6931,2741 h50
  text "OTHER +/-" at 12233.46,2613.83 h60
  text "DRILLING:" at 11132.46,2475.34 h60
  text "REFERENCE:" at 11207.23,2358.34 h60
  text "X" at 11855.46,2358.34 h60
  text "AS SHOWN" at 12042.46,2358.34 h60
  text "X" at 12756.46,2358.34 h60
  text "NC_DRILL FILES" at 12893.46,2358.34 h60
  text "PTH MIN COPPER THICKNESS:" at 11207.23,2200.34 h60
  text "X" at 12557.46,2200.34 h60
  text "1MIL" at 12694.46,2200.34 h60
  text "OTHER" at 13191.46,2200.34 h60
  text "BOARD FINISH:" at 11132.46,2041.34 h60
  text "SILKSCREEN:" at 11287.68,1923.34 h60
  text "X" at 12236.46,1923.34 h60
  text "TOP" at 12362.46,1923.34 h60
  text "X" at 12746.46,1923.34 h60
  text "BOTTOM" at 12873.46,1923.34 h60
  text "SILKSCREEN COLOR:" at 11287.68,1756.34 h60
  text "X" at 12235.42,1756.34 h60
  text "WHITE" at 12362.46,1756.34 h60
  text "OTHER" at 12873.46,1756.34 h60
  text "X" at 12443.42,1593.14 h60
  text "MATTE" at 12562.64,1592.29 h60
  text "SOLDER RESIST COLOR:" at 11287.68,1586.34 h60
  text "X" at 11855.42,1427.14 h60
  text "GREEN" at 11982.46,1427.14 h60
  text "BLUE" at 12573.46,1427.14 h60
  text "OTHER" at 13111.46,1427.14 h60
  text "IMMERSION GOLD (ENIG)" at 12193.46,1238.62 h60
  text "ENEPIG" at 13531,1235.34 h60
  text "SURFACE FINISH:" at 11132.46,1234.34 h60
  text "X" at 12006.51,1234.34 h60
  text "IMM. TIN/SILVER OR EQUIV" at 11462,1077.34 h60
  text "OTHER" at 12893.46,1077.34 h60
  text "ARRAY/PANEL:" at 11132.46,898.34 h60
  text "X" at 12015.46,896.34 h60
  text "CUT AND TRIM PER MECH LAYER 1" at 12193.46,894.05 h60
  text "N.C. ROUTE" at 12193.46,742.34 h60
  text "V. SCORE" at 13059.46,742.34 h60
  text "CERTIFICATION:" at 11132.46,605.34 h60
  text "MATERIALS AND WORKMANSHIP FOR ALL PCBS" at 11857.46,605.34 h60
  text "TO MEET OR EXCEED THE REQUIREMENTS OF:" at 11857.46,507.34 h60
  text "X" at 11483.96,370.83 h60
  text "ANSI IPC-A-600F CLASS ->" at 11622.96,370.83 h60
  text "X" at 13262.02,370.83 h60
  text "2" at 13380.96,370.84 h60
  text "1" at 13065.96,369.34 h60
  text "3" at 13734.96,369.34 h60
  text "X" at 11486.02,211.34 h60
  text "UL 94V-0" at 11622.96,211.34 h60
  text "X" at 12298.02,211.34 h60
  text "RoHS" at 12434.96,211.34 h60
  text "OTHER" at 13079.36,211.34 h60
  text "PER ORDER" at 13476.42,211.34 h60
  text "ADDITIONAL REQUIREMENTS:" at 11132.46,70.34 h60
  text "MICROSECTION:" at 11207.23,-44.66 h60
  text "YES" at 12112.96,-44.66 h60
  text "REQUIRED" at 12974.46,-200.81 h60
  text "BARE BOARD ELEC. TEST:" at 11207.23,-203.66 h60
  text "NONE" at 12512.96,-203.66 h60
  text "X" at 12847.46,-203.66 h60
  text "PER ORDER" at 13566.46,-203.66 h60
  text "MANUFACTURER'S UL:" at 11207.23,-360.66 h60
  text "RAIL" at 12372.96,-364.95 h60
  text "METAL" at 12864.77,-364.95 h60
  text "X" at 13240,-365.3 h60
  text "SILK" at 13376.46,-364.95 h60
  text "Impedance Control:" at 7928,-682.3 h60
  text "Differential Controlled to 100 Ohms (+/-10%)" at 8052,-823 h60
  text "All 6 mil traces with 12 mil spacing on Layers 1 and 6" at 8538,-970.3 h60
  text "Single Ended Controlled to 50 Ohms (+/-10%)" at 8026,-1158 h60
  text "All 8 mil traces on Layers 1, 3, and 6" at 8531,-1281 h60
  text "Differential Controlled to 90 Ohms (+/-10%)" at 8060,-1481.3 h60
  text "All 5 mil traces with 4.6 mil spacing on Layers 1 and 6" at 8385,-1631.3 h60
  text "All 5 mil traces with 6.1 mil spacing on Layer 3" at 8385,-1771.3 h60
M11 Gerber Information:
  lines w10: -492,-2245.47 6108,-2245.47 ; -492,-2042.13 6110,-2042.13 ; -492,-1838.8 -492,-2448.8 3513,-2448.8 6110,-2448.8 6110,-1838.8 -491.5,-1838.8 -491.5,-2448.8 1084,-2448.8 ; 1973,-2448.8 1973,-1838.8 ; 3240,-2042.13 3240,-1838.8 ; 4080,-2042.13 4080,-1838.8 ; 4702,-2455.3 4702,-2252.47
  text "ALL ARTWORK VIEWED FROM TOP SIDE" at -428.5,-1970.97 h60
  text "BOARD #:" at 2048,-1970.97 h60
  text "REV:" at 3438,-1970.97 h60
  text ".PCB_rev" at 3729.5,-1970.97 h60
  text "SVN REV:" at 4276,-1970.97 h60
  text ".VersionControl_RevNumber" at 4782,-1970.97 h60
  text ".PRJ_Number" at 2557,-1977 h50
  text "LAYER NAME =" at -428.5,-2173.79 h60
  text "TID #:" at 2048,-2174.3 h60
  text "NA" at 2593.5,-2174.3 h60
  text "PLOT NAME =" at -467,-2379 h50
  text "GENERATED    :" at 2050,-2379.64 h60
  text ".Print_Date" at 2919.5,-2379.64 h60
  text ".Print_Time" at 3648.5,-2379.64 h60
  text "TEXAS INSTRUMENTS" at 4913,-2379.64 h60
  text ".plot_File_Name" at 95,-2383 h50
M12 Stackup:
  drawing of 399 lines, arcs and shapes, not listed
  text "Layer" at 10238.28,6403 h50
  text "Name" at 10583.21,6403 h50
  text "Material" at 11361.33,6403 h50
  text "Thickness" at 12081.14,6403 h50
  text "Constant" at 12626,6403 h50
  text "Board Layer Stack" at 13104.22,6403 h50
  text "1" at 10238.28,6303 h50
  text "Top Overlay" at 10583.21,6303 h50
  text "2" at 10238.28,6203 h50
  text "Top Solder" at 10583.21,6203 h50
  text "Solder Resist" at 11361.33,6203 h50
  text "0.70mil" at 12081.14,6203 h50
  text "3.5" at 12626,6203 h50
  text "3" at 10238.28,6103 h50
  text "Top Layer" at 10583.21,6103 h50
  text "Copper" at 11361.33,6103 h50
  text "1.40mil" at 12081.14,6103 h50
  text "4" at 10238.28,6003 h50
  text "Dielectric 1" at 10583.21,6003 h50
  text "FR-4 High Tg" at 11361.33,6003 h50
  text "5.00mil" at 12081.14,6003 h50
  text "4.6" at 12626,6003 h50
  text "5" at 10238.28,5903 h50
  text "GND" at 10583.21,5903 h50
  text "Copper" at 11361.33,5903 h50
  text "1.40mil" at 12081.14,5903 h50
  text "6" at 10238.28,5803 h50
  text "Dielectric  2" at 10583.21,5803 h50
  text "FR-4 High Tg" at 11361.33,5803 h50
  text "5.00mil" at 12081.14,5803 h50
  text "4.6" at 12626,5803 h50
  text "7" at 10238.28,5703 h50
  text "SIG1" at 10583.21,5703 h50
  text "Copper" at 11361.33,5703 h50
  text "1.40mil" at 12081.14,5703 h50
  text "8" at 10238.28,5603 h50
  text "Dielectric 3" at 10583.21,5603 h50
  text "FR-4 High Tg" at 11361.33,5603 h50
  text "32.00mil" at 12081.14,5603 h50
  text "4.6" at 12626,5603 h50
  text "9" at 10238.28,5503 h50
  text "SIG2" at 10583.21,5503 h50
  text "Copper" at 11361.33,5503 h50
  text "1.40mil" at 12081.14,5503 h50
  text "10" at 10238.28,5403 h50
  text "Dielectric 4" at 10583.21,5403 h50
  text "FR-4 High Tg" at 11361.33,5403 h50
  text "5.00mil" at 12081.14,5403 h50
  text "4.6" at 12626,5403 h50
  text "11" at 10238.28,5303 h50
  text "GND1" at 10583.21,5303 h50
  text "Copper" at 11361.33,5303 h50
  text "1.40mil" at 12081.14,5303 h50
  text "12" at 10238.28,5203 h50
  text "Dielectric 5" at 10583.21,5203 h50
  text "FR-4 High Tg" at 11361.33,5203 h50
  text "5.00mil" at 12081.14,5203 h50
  text "4.6" at 12626,5203 h50
  text "13" at 10238.28,5103 h50
  text "Bottom Layer" at 10583.21,5103 h50
  text "Copper" at 11361.33,5103 h50
  text "1.40mil" at 12081.14,5103 h50
  text "14" at 10238.28,5003 h50
  text "Bottom Solder" at 10583.21,5003 h50
  text "Solder Resist" at 11361.33,5003 h50
  text "0.70mil" at 12081.14,5003 h50
  text "3.5" at 12626,5003 h50
  text "15" at 10238.28,4903 h50
  text "Bottom Overlay" at 10583.21,4903 h50
M13 Component Bodies Top:
  text ".Layer_Name" at 377,-2173.79 h60
M14 Component Bodies Bottom:
  text ".Layer_Name" at 377,-2173.79 h60
M15 Courtyards Top:
  text ".Layer_Name" at 377,-2173.79 h60
M16 Courtyards Bottom:
  text ".Layer_Name" at 377,-2173.79 h60
Drill Drawing:
  drawing of 159 lines, arcs and shapes, not listed
  text "Symbol" at 7000.98,6044 h36
  text "Count" at 7257.12,6044 h36
  text "Hole Size" at 7579.03,6044 h36
  text "Plated" at 8155.86,6044 h36
  text "Hole Tolerance" at 8412,6044 h36
  text "Hole Length" at 8958.84,6044 h36
  text "74" at 7257.12,5969 h30
  text "7.87mil (0.200mm)" at 7579.03,5969 h30
  text "PTH" at 8155.86,5969 h30
  text "+0.00mil/-7.87mil" at 8412,5969 h30
  text "-" at 8958.84,5969 h30
  text "A" at 6985.75,5963.01 h33.33
  text "48" at 7257.12,5894 h30
  text "10.00mil (0.254mm)" at 7579.03,5894 h30
  text "NPTH" at 8155.86,5894 h30
  text "+/-2.00mil" at 8412,5894 h30
  text "-" at 8958.84,5894 h30
  text "43" at 7257.12,5819 h30
  text "10.00mil (0.254mm)" at 7579.03,5819 h30
  text "PTH" at 8155.86,5819 h30
  text "+0.00mil/-10.00mil" at 8412,5819 h30
  text "-" at 8958.84,5819 h30
  text "C" at 6985.75,5813.01 h33.33
  text "969" at 7257.12,5744 h30
  text "12.00mil (0.305mm)" at 7579.03,5744 h30
  text "PTH" at 8155.86,5744 h30
  text "+0.00mil/-12.00mil" at 8412,5744 h30
  text "-" at 8958.84,5744 h30
  text "B" at 6985.75,5738.01 h33.33
  text "11" at 7257.12,5669 h30
  text "17.72mil (0.450mm)" at 7579.03,5669 h30
  text "PTH" at 8155.86,5669 h30
  text "+/-3.00mil" at 8412,5669 h30
  text "-" at 8958.84,5669 h30
  text "2" at 7257.12,5594 h30
  text "23.62mil (0.600mm)" at 7579.03,5594 h30
  text "PTH" at 8155.86,5594 h30
  text "+/-3.00mil" at 8412,5594 h30
  text "51.18mil (1.300mm)" at 8958.84,5594 h30
  text "2" at 7257.12,5519 h30
  text "27.56mil (0.700mm)" at 7579.03,5519 h30
  text "PTH" at 8155.86,5519 h30
  text "+/-3.00mil" at 8412,5519 h30
  text "33.47mil (0.850mm)" at 8958.84,5519 h30
  text "8" at 7257.12,5444 h30
  text "35.04mil (0.890mm)" at 7579.03,5444 h30
  text "PTH" at 8155.86,5444 h30
  text "+/-3.00mil" at 8412,5444 h30
  text "-" at 8958.84,5444 h30
  text "12" at 7257.12,5369 h30
  text "35.43mil (0.900mm)" at 7579.03,5369 h30
  text "PTH" at 8155.86,5369 h30
  text "+/-3.00mil" at 8412,5369 h30
  text "-" at 8958.84,5369 h30
  text "2" at 7257.12,5294 h30
  text "39.37mil (1.000mm)" at 7579.03,5294 h30
  text "PTH" at 8155.86,5294 h30
  text "+/-3.00mil" at 8412,5294 h30
  text "118.11mil (3.000mm)" at 8958.84,5294 h30
  text "1" at 7257.12,5219 h30
  text "39.37mil (1.000mm)" at 7579.03,5219 h30
  text "PTH" at 8155.86,5219 h30
  text "+/-3.00mil" at 8412,5219 h30
  text "137.79mil (3.500mm)" at 8958.84,5219 h30
  text "115" at 7257.12,5144 h30
  text "40.00mil (1.016mm)" at 7579.03,5144 h30
  text "PTH" at 8155.86,5144 h30
  text "+/-3.00mil" at 8412,5144 h30
  text "-" at 8958.84,5144 h30
  text "6" at 7257.12,5069 h30
  text "51.18mil (1.300mm)" at 7579.03,5069 h30
  text "PTH" at 8155.86,5069 h30
  text "+/-3.00mil" at 8412,5069 h30
  text "-" at 8958.84,5069 h30
  text "2" at 7257.12,4994 h30
  text "61.81mil (1.570mm)" at 7579.03,4994 h30
  text "PTH" at 8155.86,4994 h30
  text "+/-3.00mil" at 8412,4994 h30
  text "-" at 8958.84,4994 h30
  text "16" at 7257.12,4919 h30
  text "106.00mil (2.692mm)" at 7579.03,4919 h30
  text "PTH" at 8155.86,4919 h30
  text "+/-3.00mil" at 8412,4919 h30
  text "-" at 8958.84,4919 h30
  text "8" at 7257.12,4844 h30
  text "125.98mil (3.200mm)" at 7579.03,4844 h30
  text "PTH" at 8155.86,4844 h30
  text "+/-3.00mil" at 8412,4844 h30
  text "-" at 8958.84,4844 h30
  text "2" at 7257.12,4769 h30
  text "128.00mil (3.251mm)" at 7579.03,4769 h30
  text "PTH" at 8155.86,4769 h30
  text "+/-3.00mil" at 8412,4769 h30
  text "-" at 8958.84,4769 h30
  text "1321 Total" at 7257.12,4694 h30
  text "Slot definitions :" at 7000.98,4619.51 h30
  text "Routed Path Length" at 7520.12,4619.51 h30
  text "= Calculated from tool start centre position to tool end centre position." at 8074.26,4619.51 h30
  text "Hole Length" at 7520.12,4567.53 h30
  text "= Routed Path Length + Tool Size = Slot length as defined in the PCB layout" at 7869.32,4567.53 h30
  text ".Layer_Name" at 377,-2173.79 h60
M17 Embedded Cavity:
  text ".Layer_Name" at 480,-2173.79 h60
M18 Embedded Assembly:
  text ".Layer_Name" at 480,-2173.79 h60
M19 Embedded Keepout:
  text ".Layer_Name" at 480,-2173.79 h60
Mechanical 20:
  lines w10: -200,-160 ccw(c-160,-160) -160,-200 6350.55,-200 ccw(c6350.55,-160) 6390.55,-160 6390.55,860.94 6236.02,860.94 cw(c6235.46,893.9) 6202.5,893.34 cw(c6236.53,893.85) 6236.02,927.87 6390.55,927.87 6390.55,6153.7 ccw(c6350.55,6153.7) 6350.55,6193.7 -160,6193.7 ccw(c-160,6153.7) -200,6153.7 -200,-160
Mechanical 21:
  lines w10: 6871.81,2430.09 6591.84,2430.09 cw(c6591.84,2480.09) 6541.84,2480.09 6541.84,2548.09 cw(c6591.84,2548.09) 6591.84,2598.09 6871.81,2598.09 ; 6950.55,2430.09 7301.13,2430.09 ; 6950.55,2598.09 7301,2598.09 ; 7301.13,2430.21 ccw(c7301.13,2480.21) 7351.13,2480.21 7351.13,2548.21 ccw(c7301.13,2548.21) 7301.13,2598.21 ; 7951.65,2430.39 7671.68,2430.39 cw(c7671.68,2480.39) 7621.68,2480.39 7621.68,2548.39 cw(c7671.68,2548.39) 7671.68,2598.39 7951.65,2598.39 ; 8030.39,2430.39 8380.97,2430.39 ; 8030.39,2598.39 8380.84,2598.39 ; 8380.97,2430.52 ccw(c8380.97,2480.52) 8430.97,2480.52 8430.97,2548.52 ccw(c8380.97,2548.52) 8380.97,2598.52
